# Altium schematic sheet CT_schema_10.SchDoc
size 278 x 170 mm
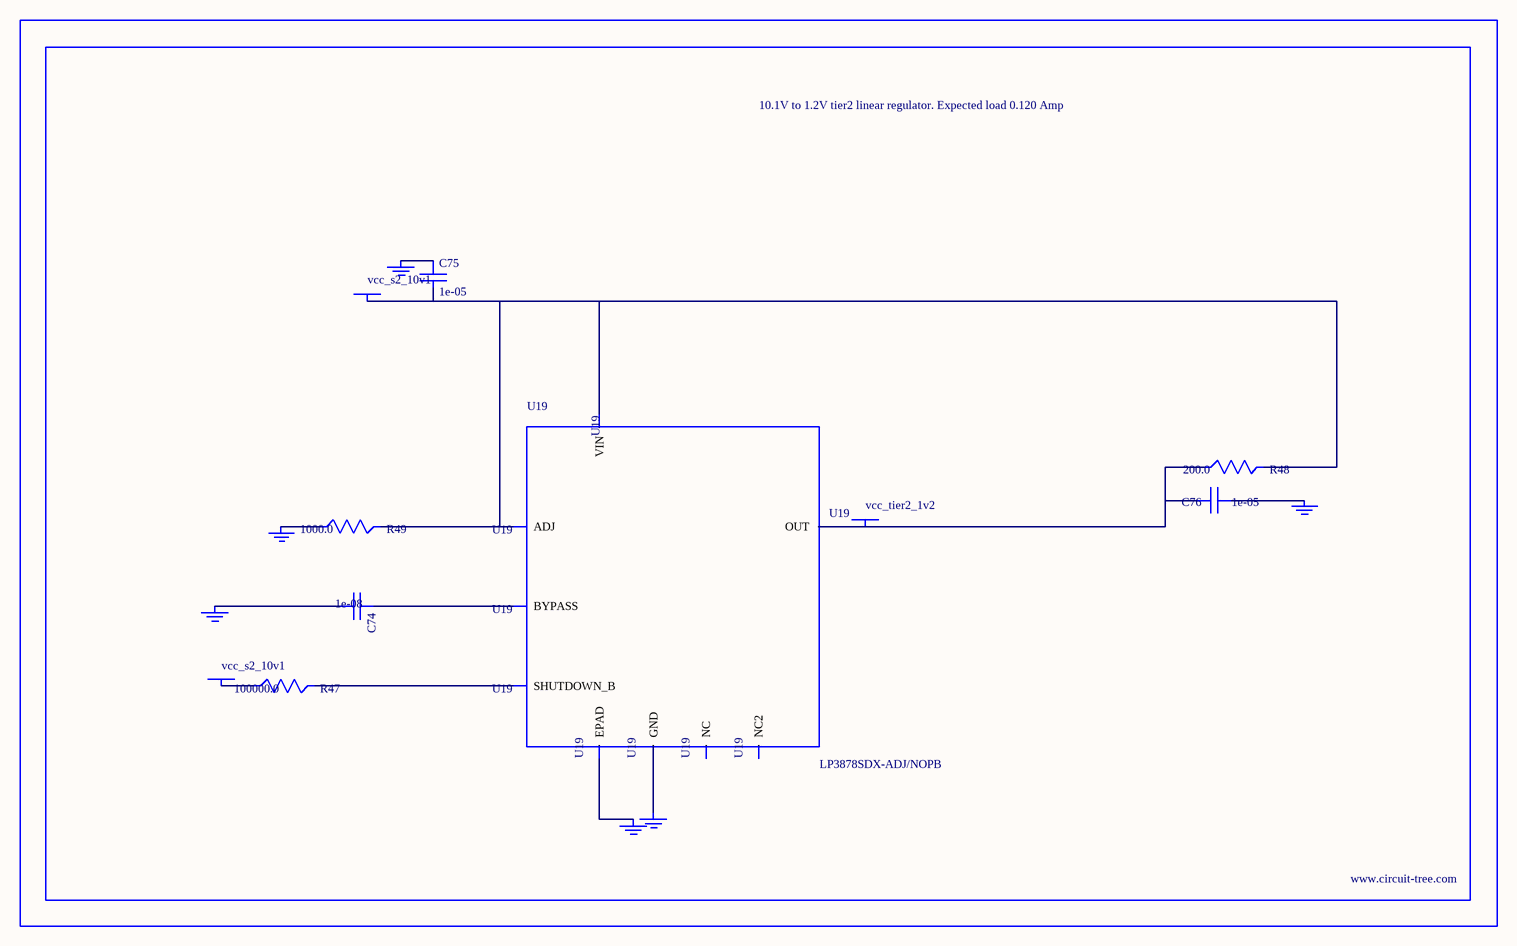
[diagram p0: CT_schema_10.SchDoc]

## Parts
BORDER9  (no value)
C74  1e-08  [C0402]
C75  1e-05  [C1206]
C76  1e-05  [C0805]
GND_INSTANCE_9_0  (no value)
GND_INSTANCE_9_1  (no value)
GND_INSTANCE_9_2  (no value)
GND_INSTANCE_9_3  (no value)
GND_INSTANCE_9_4  (no value)
GND_INSTANCE_9_5  (no value)
POWER_INSTANCE_9_0  vcc_s2_10v1
POWER_INSTANCE_9_1  vcc_s2_10v1
POWER_INSTANCE_9_2  vcc_tier2_1v2
R47  100000.0  [R0603]
R48  200.0  [R0603]
R49  1000.0  [R0603]
U19  LP3878SDX-ADJ/NOPB  [WSON-8]

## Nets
NetC74_1: C74.1 U19.1(BYPASS)
NetC74_2: C74.2 GND_INSTANCE_9_0.0(GND)
NetC75_1: C75.1 GND_INSTANCE_9_1.0(GND)
NetC75_2: C75.2 POWER_INSTANCE_9_0.0(PWR) R48.2 R49.2 U19.4(VIN) U19.6(ADJ)
NetC76_1: C76.1 GND_INSTANCE_9_2.0(GND)
NetC76_2: C76.2 POWER_INSTANCE_9_2.0(PWR) R48.1 U19.5(OUT)
NetGND_INSTANCE_9_3_0: GND_INSTANCE_9_3.0(GND) R49.1
NetGND_INSTANCE_9_4_0: GND_INSTANCE_9_4.0(GND) U19.PAD(EPAD)
NetGND_INSTANCE_9_5_0: GND_INSTANCE_9_5.0(GND) U19.3(GND)
NetPOWER_INSTANCE_9_1_0: POWER_INSTANCE_9_1.0(PWR) R47.1
NetR47_2: R47.2 U19.8(SHUTDOWN_B)

Not connected (* = marked no-connect by the designer): U19 2(NC) 7(NC2)

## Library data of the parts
BORDER9 = BORDER_PAGE9
C74 = C0402C103K3RAC
C75 = C1206C106K3RACTU
C76 = GRM219R60J106ME19D
GND_INSTANCE_9_0-GND_INSTANCE_9_5 = GND
POWER_INSTANCE_9_0-POWER_INSTANCE_9_2 = PWR
R47 = RC0603JR-07100KL
R48 = RC0603JR-07200RL
R49 = RC0603JR-071KL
